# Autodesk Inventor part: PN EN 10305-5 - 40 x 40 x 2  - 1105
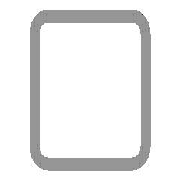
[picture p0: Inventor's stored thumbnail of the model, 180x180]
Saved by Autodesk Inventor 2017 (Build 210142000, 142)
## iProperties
_CCFamilyMember: 26
_CCFamilyDisplayName: PN EN 10305-5 (Rury kwadratowe, spawane, wymiarowane na zimno) - Rury stalowe do zastosowań precyzyjnych -  (Część 5: Rury kwadratowe, spawane, wymiarowane na z
_FrameMemberDoc: Frame Member File
_Version: 15.0.0
_GetPNFromCC: 1
Created: 2016-02
Part Number: PN EN 10305-5 - 40 x 40 x 2  - 1105
Material: Stal, miękka
Description: Rury stalowe do zastosowań precyzyjnych -  (Część 5: Rury kwadratowe, spawane, wymiarowane na zimno)
Document SubType Name: Modeling
Standard: PN
Designer: X
Standards Organization: PN
Language: pl-PL
Size Designation: 40 x 40 x 2
Categories: <MemberInstance><Categories><Category DisplayName="Kształtowniki konstrukcyjne" InternalName="089c4875-fa83-4c05-b084-43b9cc11f5ed" Mnemonic="GRDR"><CategoryPar
Stock Number: 40 x 40 x 2
Density: 7.85 g/cm^3
Appearance: Częściowo polerowana
IsCustomPart: 1
G_L: 1105,000 mm
G_W: 40,000 mm
G_H: 40,000 mm
Author: X
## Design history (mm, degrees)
node "Płaszczyzna początkowa"
node "Płaszczyzna końcowa"
sketch "Szkic"
  geometry: L1 (-20, -17)-(-20, 17); L2 (-17, 20)-(17, 20); L3 (20, 17)-(20, -17); L4 (17, -20)-(-17, -20); L5 (-17, 18)-(17, 18); L6 (18, 17)-(18, -17); L7 (17, -18)-(-17, -18); L8 (-18, -17)-(-18, 17); L9 (0, 25.37)-(0, -25.37) reference; L10 (-25.37, 0)-(25.37, 0) reference; A1 r 3 centre (-17, -17) between (-20, -17) and (-17, -20); A2 r 3 centre (-17, 17) between (-17, 20) and (-20, 17); A3 r 3 centre (17, 17) between (20, 17) and (17, 20); A4 r 3 centre (17, -17) between (17, -20) and (20, -17); A5 r 1 centre (-17, 17) between (-17, 18) and (-18, 17); A6 r 1 centre (17, 17) between (18, 17) and (17, 18); A7 r 1 centre (17, -17) between (17, -18) and (18, -17); A8 r 1 centre (-17, -17) between (-18, -17) and (-17, -18)
  constraints: 16 end point, 16 point on circle, 8 centre point, 8 tangent, 4 parallel, 3 equal radius, 2 perpendicular, 7 other
  dimensions: "d7" = 3 radius of A1 (= G_IR); "d10" = 40 distance between parallel lines of L2 L4 (= G_H); "d11" = 40 distance between parallel lines of L1 L3 (= G_W); "d12" = 2 distance between parallel lines of L3 L6 (= G_T); "d15" = 20 distance between parallel lines of L2 L10 (= 0.5 x d10); "d16" = 20 distance between parallel lines of L9 L3 (= 0.5 x d11)
extrude "Bryła" new body sketch "Szkic" stored distance "d3" = 1105 (= G_L); taper "d4" = 0 deg
node "Driven Length"
  sketch "Sketch3"
    geometry: L1 (0, 0)-(10, 0) reference
    constraints: 2 end point, 1 horizontal
  workplane "Work Plane3"
  sketch "Sketch4"
    geometry: L1 (-2, 0)-(12, 0) reference; L2 (-2, 1105)-(12, 1105) reference
    dimensions: "d18" = 1105 distance between parallel lines of L1 L2 (derived)
body "Solid1"
other parameters: "G_W" = 40 [user parameter; used in 1 equation term], "G_H" = 40 [user parameter; used in 1 equation term], "G_T" = 2 [user parameter; used in 1 equation term], "G_IR" = 3 [user parameter; used in 1 equation term], "G_L" = 1105 (= d18) [user parameter; used in 1 equation term], "G_OFFSET_START" = 0 [user parameter; used in 1 equation term], "G_OFFSET_END" = -35 [user parameter; used in 1 equation term], "d13" = 0 (computed from G_OFFSET_START), "d14" = 1105 (= G_OFFSET_END + B_L), "d17" = 90 deg
